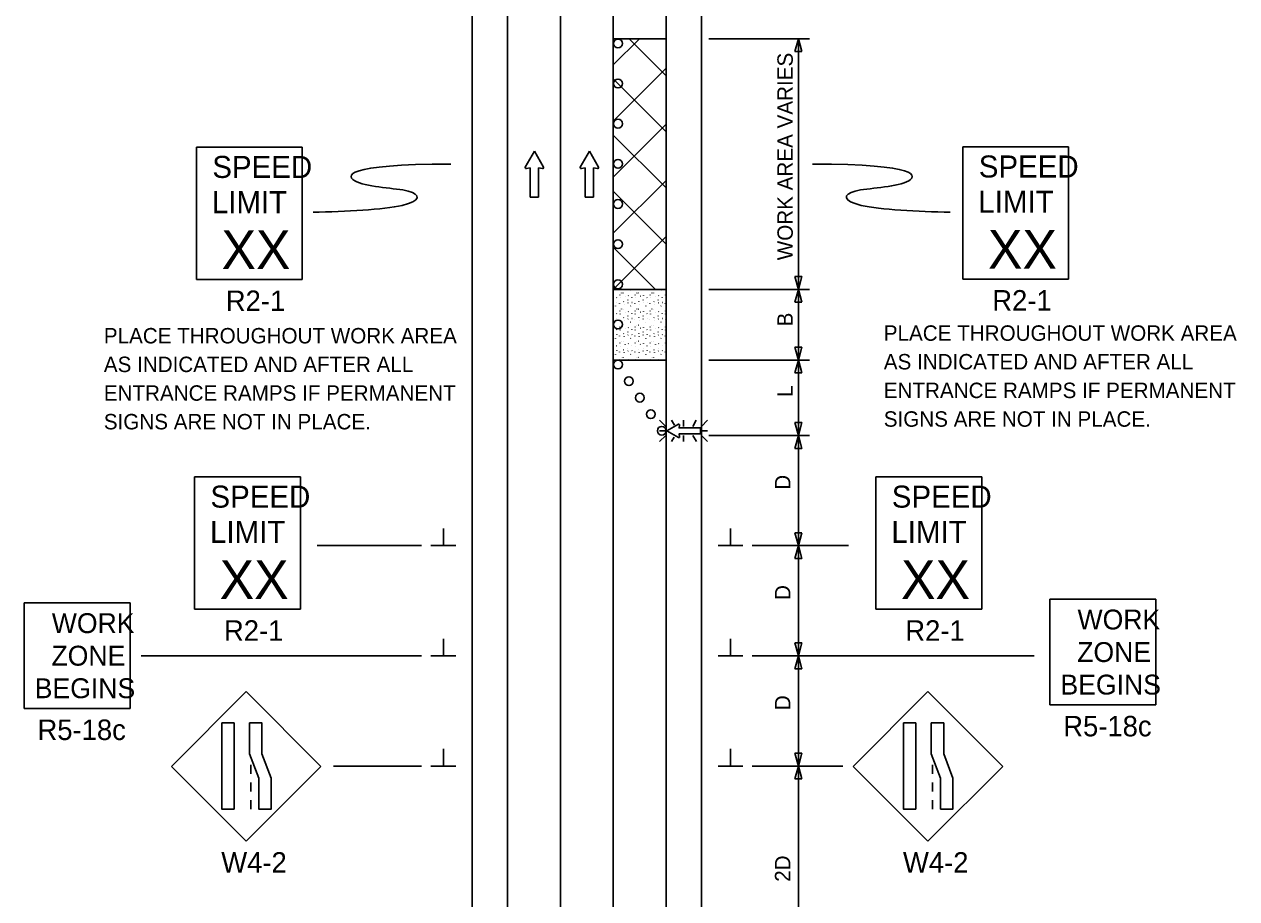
# Model space of a CAD drawing. Extents: x 16741 to 18475, y 7000 to 8315.
# Drawn here: x 16748 to 17298, y 7658 to 8055 of the extents above; entities that cross this region are included whole.
import ezdxf

# ---------------------------------------------------------------- set-up
doc = ezdxf.new("R2010")
doc.units = 0
for name, color, linetype in [('ALI_LEGAL_EX', 7, 'Continuous'), ('MT_SCRATCH_LEVEL_E', 7, 'Continuous'), ('PAVT_EDGE_EX', 7, 'Continuous'), ('TRAFFIC_SIGNS_PR', 7, 'Continuous'), ('TYPICAL_TEXT_DIMEN_PR', 7, 'Continuous')]:
    doc.layers.add(name, color=color, linetype=linetype)

msp = doc.modelspace()

# ---------------------------------------------------------------- linework, layer by layer
at = {"layer": 'ALI_LEGAL_EX'}
for p, q in [((16991.15, 8188.6), (16991.15, 7369.05)), ((17015.15, 8188.6), (17015.15, 7369.05))]:
    msp.add_line(p, q, dxfattribs=at)
for points in [[(16991.15, 7988.6), (16991.15, 7963.6)], [(17015.15, 7988.6), (17015.15, 7963.6)], [(16991.15, 7888.6), (16991.15, 7863.6)], [(16991.15, 7788.6), (16991.15, 7763.6)], [(17015.15, 7788.6), (17015.15, 7763.6)], [(16991.15, 7688.6), (16991.15, 7663.6)], [(17015.15, 7688.6), (17015.15, 7663.6)]]:
    msp.add_lwpolyline(points, dxfattribs=at)
at = {"layer": 'MT_SCRATCH_LEVEL_E'}
for p, q in [((16979.32, 7997.1), (16975.21, 7989.86)), ((16983.46, 7989.86), (16979.32, 7997.1)), ((17004.27, 7997.1), (17000.16, 7989.86)), ((17008.42, 7989.86), (17004.27, 7997.1)), ((16975.69, 7989.18), (16977.46, 7989.49)), ((16977.46, 7989.49), (16977.46, 7976.24)), ((16981.21, 7976.24), (16981.21, 7989.49)), ((16981.21, 7989.49), (16982.98, 7989.18)), ((17000.64, 7989.18), (17002.42, 7989.49)), ((17002.42, 7989.49), (17002.42, 7976.24)), ((17006.16, 7976.24), (17006.16, 7989.49)), ((17006.16, 7989.49), (17007.94, 7989.18)), ((16977.46, 7976.24), (16981.21, 7976.24)), ((17002.42, 7976.24), (17006.16, 7976.24))]:
    msp.add_line(p, q, dxfattribs=at)
for centre, start, end in [((16975.61, 7989.64), 150.4248, 279.9638), ((16983.05, 7989.64), 260.0362, 29.7731), ((17000.56, 7989.64), 150.4248, 279.9638), ((17008.01, 7989.64), 260.0362, 29.7731)]:
    msp.add_arc(centre, 0.463, start, end, dxfattribs=at)
at = {"layer": 'PAVT_EDGE_EX'}
for p, q in [((17015.15, 8314.85), (17015.15, 7485.67)), ((16951.15, 8188.6), (16951.15, 7369.05)), ((16967.15, 8188.6), (16967.15, 7369.05)), ((17039.15, 8188.6), (17039.15, 7369.05)), ((17055.15, 8188.6), (17055.15, 7369.05)), ((17039.15, 8048.11), (17015.15, 8048.11)), ((17015.15, 8048.11), (17039.15, 8048.11)), ((17015.15, 8036.2), (17027.06, 8048.11)), ((17039.15, 8031.3), (17022.34, 8048.11)), ((17039.15, 7934.38), (17039.15, 8048.11)), ((17015.15, 8010.75), (17039.15, 8034.75)), ((17039.15, 8005.84), (17015.15, 8029.84)), ((17015.15, 7985.29), (17039.15, 8009.29)), ((17039.15, 7980.39), (17015.15, 8004.39)), ((17015.15, 7959.84), (17039.15, 7983.84)), ((17039.15, 7954.93), (17015.15, 7978.93)), ((17015.15, 7934.38), (17039.15, 7958.38)), ((17034.24, 7934.38), (17015.15, 7953.47)), ((17015.15, 7934.38), (17039.15, 7934.38)), ((17015.15, 7934.38), (17039.15, 7934.38)), ((17039.15, 7934.38), (17015.15, 7934.38)), ((17015.15, 7934.38), (17015.15, 7934.38)), ((17016.08, 7934.02), (17016.13, 7934.14)), ((17022.97, 7934.02), (17023.02, 7934.14)), ((17029.85, 7934.02), (17029.91, 7934.14)), ((17036.74, 7934.02), (17036.8, 7934.14)), ((17039.15, 7902.32), (17039.15, 7934.38)), ((17016.65, 7930.7), (17016.7, 7930.62)), ((17018.1, 7931.83), (17018.15, 7931.94)), ((17018.18, 7930.56), (17018.23, 7930.48)), ((17018.86, 7932.79), (17018.92, 7932.71)), ((17019.6, 7932.76), (17019.65, 7932.68)), ((17019.82, 7928.77), (17019.87, 7928.89)), ((17020.47, 7931.38), (17020.52, 7931.3)), ((17021.75, 7929.64), (17021.8, 7929.56)), ((17021.92, 7931.53), (17021.97, 7931.65)), ((17023.54, 7930.7), (17023.59, 7930.62)), ((17024.99, 7931.83), (17025.04, 7931.94)), ((17025.07, 7930.56), (17025.12, 7930.48)), ((17025.75, 7932.79), (17025.8, 7932.71)), ((17026.49, 7932.76), (17026.54, 7932.68)), ((17026.71, 7928.77), (17026.76, 7928.89)), ((17027.36, 7931.38), (17027.41, 7931.3)), ((17028.64, 7929.64), (17028.69, 7929.56)), ((17028.81, 7931.53), (17028.86, 7931.65)), ((17030.42, 7930.7), (17030.48, 7930.62)), ((17031.88, 7931.83), (17031.93, 7931.94)), ((17031.96, 7930.56), (17032.01, 7930.48)), ((17032.64, 7932.79), (17032.69, 7932.71)), ((17033.38, 7932.76), (17033.43, 7932.68)), ((17033.6, 7928.77), (17033.65, 7928.89)), ((17034.24, 7931.38), (17034.3, 7931.3)), ((17035.52, 7929.64), (17035.57, 7929.56)), ((17035.69, 7931.53), (17035.75, 7931.65)), ((17037.31, 7930.7), (17037.36, 7930.62)), ((17038.76, 7931.83), (17038.81, 7931.94)), ((17038.84, 7930.56), (17038.89, 7930.48)), ((17016.08, 7926.74), (17016.13, 7926.86)), ((17016.65, 7923.41), (17016.7, 7923.34)), ((17016.7, 7928.49), (17016.75, 7928.41)), ((17017.98, 7927.91), (17017.99, 7927.8)), ((17018.1, 7924.54), (17018.15, 7924.66)), ((17018.18, 7923.28), (17018.23, 7923.2)), ((17018.86, 7925.5), (17018.92, 7925.42)), ((17019.6, 7925.47), (17019.65, 7925.39)), ((17020.01, 7927.57), (17020.06, 7927.49)), ((17020.47, 7924.09), (17020.52, 7924.02)), ((17021.79, 7928.24), (17021.84, 7928.36)), ((17021.92, 7924.24), (17021.97, 7924.36)), ((17022.97, 7926.74), (17023.02, 7926.86)), ((17023.54, 7923.41), (17023.59, 7923.34)), ((17023.59, 7928.49), (17023.64, 7928.41)), ((17024.87, 7927.91), (17024.88, 7927.8)), ((17024.99, 7924.54), (17025.04, 7924.66)), ((17025.07, 7923.28), (17025.12, 7923.2)), ((17025.75, 7925.5), (17025.8, 7925.42)), ((17026.49, 7925.47), (17026.54, 7925.39)), ((17026.9, 7927.57), (17026.95, 7927.49)), ((17027.36, 7924.09), (17027.41, 7924.02)), ((17028.68, 7928.24), (17028.73, 7928.36)), ((17028.81, 7924.24), (17028.86, 7924.36)), ((17029.85, 7926.74), (17029.91, 7926.86)), ((17030.42, 7923.41), (17030.48, 7923.34)), ((17030.47, 7928.49), (17030.53, 7928.41)), ((17031.76, 7927.91), (17031.77, 7927.8)), ((17031.88, 7924.54), (17031.93, 7924.66)), ((17031.96, 7923.28), (17032.01, 7923.2)), ((17032.64, 7925.5), (17032.69, 7925.42)), ((17033.38, 7925.47), (17033.43, 7925.39)), ((17033.78, 7927.57), (17033.84, 7927.49)), ((17034.24, 7924.09), (17034.3, 7924.02)), ((17035.56, 7928.24), (17035.62, 7928.36)), ((17035.69, 7924.24), (17035.75, 7924.36)), ((17036.74, 7926.74), (17036.8, 7926.86)), ((17037.31, 7923.41), (17037.36, 7923.34)), ((17037.36, 7928.49), (17037.41, 7928.41)), ((17038.64, 7927.91), (17038.66, 7927.8)), ((17038.76, 7924.54), (17038.81, 7924.66)), ((17038.84, 7923.28), (17038.89, 7923.2)), ((17016.08, 7919.45), (17016.13, 7919.57)), ((17016.7, 7921.21), (17016.75, 7921.13)), ((17017.98, 7920.63), (17017.99, 7920.51)), ((17018.86, 7918.22), (17018.92, 7918.14)), ((17019.6, 7918.19), (17019.65, 7918.11)), ((17019.82, 7921.49), (17019.87, 7921.6)), ((17020.01, 7920.29), (17020.06, 7920.21)), ((17021.75, 7922.36), (17021.8, 7922.28)), ((17021.79, 7920.95), (17021.84, 7921.07)), ((17022.97, 7919.45), (17023.02, 7919.57)), ((17023.59, 7921.21), (17023.64, 7921.13)), ((17024.87, 7920.63), (17024.88, 7920.51)), ((17025.75, 7918.22), (17025.8, 7918.14)), ((17026.49, 7918.19), (17026.54, 7918.11)), ((17026.71, 7921.49), (17026.76, 7921.6)), ((17026.9, 7920.29), (17026.95, 7920.21)), ((17028.64, 7922.36), (17028.69, 7922.28)), ((17028.68, 7920.95), (17028.73, 7921.07)), ((17029.85, 7919.45), (17029.91, 7919.57)), ((17030.47, 7921.21), (17030.53, 7921.13)), ((17031.76, 7920.63), (17031.77, 7920.51)), ((17032.64, 7918.22), (17032.69, 7918.14)), ((17033.38, 7918.19), (17033.43, 7918.11)), ((17033.6, 7921.49), (17033.65, 7921.6)), ((17033.78, 7920.29), (17033.84, 7920.21)), ((17035.52, 7922.36), (17035.57, 7922.28)), ((17035.56, 7920.95), (17035.62, 7921.07)), ((17036.74, 7919.45), (17036.8, 7919.57)), ((17037.36, 7921.21), (17037.41, 7921.13)), ((17038.64, 7920.63), (17038.66, 7920.51)), ((17016.08, 7912.17), (17016.13, 7912.28)), ((17016.65, 7916.13), (17016.7, 7916.05)), ((17016.7, 7913.92), (17016.75, 7913.84)), ((17017.98, 7913.35), (17017.99, 7913.23)), ((17018.1, 7917.26), (17018.15, 7917.37)), ((17018.18, 7915.99), (17018.23, 7915.91)), ((17019.82, 7914.2), (17019.87, 7914.32)), ((17020.01, 7913), (17020.06, 7912.92)), ((17020.47, 7916.81), (17020.52, 7916.73)), ((17021.75, 7915.07), (17021.8, 7914.99)), ((17021.79, 7913.67), (17021.84, 7913.79)), ((17021.92, 7916.96), (17021.97, 7917.07)), ((17022.97, 7912.17), (17023.02, 7912.28)), ((17023.54, 7916.13), (17023.59, 7916.05)), ((17023.59, 7913.92), (17023.64, 7913.84)), ((17024.87, 7913.35), (17024.88, 7913.23)), ((17024.99, 7917.26), (17025.04, 7917.37)), ((17025.07, 7915.99), (17025.12, 7915.91)), ((17026.71, 7914.2), (17026.76, 7914.32)), ((17026.9, 7913), (17026.95, 7912.92)), ((17027.36, 7916.81), (17027.41, 7916.73)), ((17028.64, 7915.07), (17028.69, 7914.99)), ((17028.68, 7913.67), (17028.73, 7913.79)), ((17028.81, 7916.96), (17028.86, 7917.07)), ((17029.85, 7912.17), (17029.91, 7912.28)), ((17030.42, 7916.13), (17030.48, 7916.05)), ((17030.47, 7913.92), (17030.53, 7913.84)), ((17031.76, 7913.35), (17031.77, 7913.23)), ((17031.88, 7917.26), (17031.93, 7917.37)), ((17031.96, 7915.99), (17032.01, 7915.91)), ((17033.6, 7914.2), (17033.65, 7914.32)), ((17033.78, 7913), (17033.84, 7912.92)), ((17034.24, 7916.81), (17034.3, 7916.73)), ((17035.52, 7915.07), (17035.57, 7914.99)), ((17035.56, 7913.67), (17035.62, 7913.79)), ((17035.69, 7916.96), (17035.75, 7917.07)), ((17036.74, 7912.17), (17036.8, 7912.28)), ((17037.31, 7916.13), (17037.36, 7916.05)), ((17037.36, 7913.92), (17037.41, 7913.84)), ((17038.64, 7913.35), (17038.66, 7913.23)), ((17038.76, 7917.26), (17038.81, 7917.37)), ((17038.84, 7915.99), (17038.89, 7915.91)), ((17016.65, 7908.85), (17016.7, 7908.77)), ((17016.7, 7906.64), (17016.75, 7906.56)), ((17018.1, 7909.97), (17018.15, 7910.09)), ((17018.18, 7908.7), (17018.23, 7908.63)), ((17018.86, 7910.93), (17018.92, 7910.85)), ((17019.6, 7910.9), (17019.65, 7910.82)), ((17019.82, 7906.92), (17019.87, 7907.03)), ((17020.47, 7909.52), (17020.52, 7909.45)), ((17021.75, 7907.79), (17021.8, 7907.71)), ((17021.92, 7909.67), (17021.97, 7909.79)), ((17023.54, 7908.85), (17023.59, 7908.77)), ((17023.59, 7906.64), (17023.64, 7906.56)), ((17024.99, 7909.97), (17025.04, 7910.09)), ((17025.07, 7908.7), (17025.12, 7908.63)), ((17025.75, 7910.93), (17025.8, 7910.85)), ((17026.49, 7910.9), (17026.54, 7910.82)), ((17026.71, 7906.92), (17026.76, 7907.03)), ((17027.36, 7909.52), (17027.41, 7909.45)), ((17028.64, 7907.79), (17028.69, 7907.71)), ((17028.81, 7909.67), (17028.86, 7909.79)), ((17030.42, 7908.85), (17030.48, 7908.77)), ((17030.47, 7906.64), (17030.53, 7906.56)), ((17031.88, 7909.97), (17031.93, 7910.09)), ((17031.96, 7908.7), (17032.01, 7908.63)), ((17032.64, 7910.93), (17032.69, 7910.85)), ((17033.38, 7910.9), (17033.43, 7910.82)), ((17033.6, 7906.92), (17033.65, 7907.03)), ((17034.24, 7909.52), (17034.3, 7909.45)), ((17035.52, 7907.79), (17035.57, 7907.71)), ((17035.69, 7909.67), (17035.75, 7909.79)), ((17037.31, 7908.85), (17037.36, 7908.77)), ((17037.36, 7906.64), (17037.41, 7906.56)), ((17038.76, 7909.97), (17038.81, 7910.09)), ((17038.84, 7908.7), (17038.89, 7908.63)), ((17015.15, 7902.32), (17039.15, 7902.32)), ((17015.15, 7902.32), (17039.15, 7902.32)), ((17016.08, 7904.88), (17016.13, 7905)), ((17017.98, 7906.06), (17017.99, 7905.94)), ((17018.1, 7902.69), (17018.15, 7902.8)), ((17018.86, 7903.65), (17018.92, 7903.57)), ((17019.6, 7903.62), (17019.65, 7903.54)), ((17020.01, 7905.72), (17020.06, 7905.64)), ((17021.79, 7906.39), (17021.84, 7906.5)), ((17021.92, 7902.39), (17021.97, 7902.51)), ((17022.97, 7904.88), (17023.02, 7905)), ((17024.87, 7906.06), (17024.88, 7905.94)), ((17024.99, 7902.69), (17025.04, 7902.8)), ((17025.75, 7903.65), (17025.8, 7903.57)), ((17026.49, 7903.62), (17026.54, 7903.54)), ((17026.9, 7905.72), (17026.95, 7905.64)), ((17028.68, 7906.39), (17028.73, 7906.5)), ((17028.81, 7902.39), (17028.86, 7902.51)), ((17029.85, 7904.88), (17029.91, 7905)), ((17031.76, 7906.06), (17031.77, 7905.94)), ((17031.88, 7902.69), (17031.93, 7902.8)), ((17032.64, 7903.65), (17032.69, 7903.57)), ((17033.38, 7903.62), (17033.43, 7903.54)), ((17033.78, 7905.72), (17033.84, 7905.64)), ((17035.56, 7906.39), (17035.62, 7906.5)), ((17035.69, 7902.39), (17035.75, 7902.51)), ((17036.74, 7904.88), (17036.8, 7905)), ((17038.64, 7906.06), (17038.66, 7905.94)), ((17038.76, 7902.69), (17038.81, 7902.8))]:
    msp.add_line(p, q, dxfattribs=at)
at = {"layer": 'TRAFFIC_SIGNS_PR'}
for p, q in [((16825.96, 7998.88), (16873.96, 7998.88)), ((16825.96, 7938.88), (16825.96, 7998.88)), ((16873.96, 7938.88), (16873.96, 7998.88)), ((17173.77, 7999.06), (17221.77, 7999.06)), ((17173.77, 7939.06), (17173.77, 7999.06)), ((17221.77, 7939.06), (17221.77, 7999.06)), ((16825.96, 7938.88), (16873.96, 7938.88)), ((17173.77, 7939.06), (17221.77, 7939.06)), ((17036.14, 7875.01), (17038.96, 7872.2)), ((17042.86, 7872.83), (17041.6, 7875.02)), ((17047.05, 7872.2), (17047.05, 7875.02)), ((17051.18, 7872.2), (17052.81, 7875.02)), ((17055.13, 7872.2), (17057.95, 7875.02)), ((17038.96, 7870.16), (17036.14, 7870.16)), ((17036.14, 7865.31), (17038.96, 7868.13)), ((17047.05, 7868.13), (17047.05, 7865.31)), ((17052.83, 7865.31), (17051.21, 7868.13)), ((17055.13, 7870.16), (17057.95, 7870.16)), ((17055.13, 7868.13), (17057.95, 7865.31)), ((17041.58, 7865.31), (17042.78, 7867.4)), ((16825.12, 7849.28), (16873.12, 7849.28)), ((16825.12, 7789.28), (16825.12, 7849.28)), ((16873.12, 7789.28), (16873.12, 7849.28)), ((17134.3, 7849.28), (17182.3, 7849.28)), ((17134.3, 7789.28), (17134.3, 7849.28)), ((17182.3, 7789.28), (17182.3, 7849.28)), ((16747.84, 7744.24), (16747.84, 7792.24)), ((16747.84, 7792.24), (16795.84, 7792.24)), ((16795.84, 7744.24), (16795.84, 7792.24)), ((17213.3, 7745.89), (17213.3, 7793.89)), ((17213.3, 7793.89), (17261.3, 7793.89)), ((17261.3, 7745.89), (17261.3, 7793.89)), ((16825.12, 7789.28), (16873.12, 7789.28)), ((17134.3, 7789.28), (17182.3, 7789.28)), ((16848.55, 7751.94), (16814.61, 7718)), ((16882.49, 7718), (16848.55, 7751.94)), ((17157.89, 7751.94), (17123.95, 7718)), ((17191.83, 7718), (17157.89, 7751.94)), ((16747.84, 7744.24), (16795.84, 7744.24)), ((17213.3, 7745.89), (17261.3, 7745.89)), ((16814.61, 7718), (16848.55, 7684.06)), ((16848.55, 7684.06), (16882.49, 7718)), ((16850.6, 7718.61), (16850.6, 7714.61)), ((17123.95, 7718), (17157.89, 7684.06)), ((17157.89, 7684.06), (17191.83, 7718)), ((17159.94, 7718.61), (17159.94, 7714.61)), ((16850.6, 7710.61), (16850.6, 7706.61)), ((17159.94, 7710.61), (17159.94, 7706.61)), ((16850.6, 7702.61), (16850.6, 7698.61)), ((17159.94, 7702.61), (17159.94, 7698.61))]:
    msp.add_line(p, q, dxfattribs=at)
for points in [[(17044.72, 7873.18), (17039.41, 7870.16), (17044.72, 7867.12)], [(17045.22, 7867.48), (17044.99, 7868.78), (17054.71, 7868.78), (17054.71, 7871.52), (17044.99, 7871.52), (17045.22, 7872.82)]]:
    msp.add_lwpolyline(points, dxfattribs=at)
for points in [[(16837.43, 7737.67), (16837.43, 7698.61), (16843.04, 7698.61), (16843.04, 7737.67)], [(16850.1, 7737.67), (16850.1, 7723.69), (16854.28, 7712.59), (16854.28, 7698.61), (16859.89, 7698.61), (16859.89, 7712.59), (16855.71, 7723.69), (16855.71, 7737.67)], [(17146.77, 7737.67), (17146.77, 7698.61), (17152.39, 7698.61), (17152.39, 7737.67)], [(17159.44, 7737.67), (17159.44, 7723.69), (17163.62, 7712.59), (17163.62, 7698.61), (17169.24, 7698.61), (17169.24, 7712.59), (17165.06, 7723.69), (17165.06, 7737.67)]]:
    msp.add_lwpolyline(points, close=True, dxfattribs=at)
for centre in [(17017.25, 8045.98), (17017.25, 8027.77), (17017.25, 8009.56), (17017.25, 7991.34), (17017.25, 7973.13), (17017.25, 7954.91), (17017.25, 7936.7), (17017.25, 7918.48), (17017.25, 7900.27), (17022.22, 7892.76), (17027.19, 7885.25), (17032.16, 7877.75), (17037.13, 7870.25)]:
    msp.add_circle(centre, 2, dxfattribs=at)
for centre, start, end in [((17044.89, 7872.88), 350.7308, 118.8916), ((17044.88, 7867.42), 241.4833, 9.9593)]:
    msp.add_arc(centre, 0.341, start, end, dxfattribs=at)
at = {"layer": 'TYPICAL_TEXT_DIMEN_PR'}
for p, q in [((17104.15, 8048.11), (17058.45, 8048.11)), ((17097.58, 8042.24), (17099.15, 8048.11)), ((17099.15, 7934.38), (17099.15, 8048.11)), ((17099.15, 8048.11), (17100.72, 8042.24)), ((17099.15, 8042.24), (17097.58, 8042.24)), ((17100.72, 8042.24), (17099.15, 8042.24)), ((17099.15, 7934.38), (17097.58, 7940.24)), ((17097.58, 7940.24), (17099.15, 7940.24)), ((17099.15, 7940.24), (17100.72, 7940.24)), ((17100.72, 7940.24), (17099.15, 7934.38)), ((17104.15, 7934.38), (17058.45, 7934.38)), ((17097.58, 7928.52), (17099.15, 7934.38)), ((17099.15, 7902.32), (17099.15, 7934.38)), ((17099.15, 7934.38), (17100.72, 7928.52)), ((17099.15, 7928.52), (17097.58, 7928.52)), ((17100.72, 7928.52), (17099.15, 7928.52)), ((17099.15, 7902.32), (17097.58, 7908.18)), ((17097.58, 7908.18), (17099.15, 7908.18)), ((17099.15, 7908.18), (17100.72, 7908.18)), ((17100.72, 7908.18), (17099.15, 7902.32)), ((17104.15, 7902.32), (17058.45, 7902.32)), ((17097.58, 7896.46), (17099.15, 7902.32)), ((17099.15, 7868.13), (17099.15, 7902.32)), ((17099.15, 7902.32), (17100.72, 7896.46)), ((17099.15, 7896.46), (17097.58, 7896.46)), ((17100.72, 7896.46), (17099.15, 7896.46)), ((17099.15, 7868.13), (17097.58, 7873.99)), ((17097.58, 7873.99), (17099.15, 7873.99)), ((17099.15, 7873.99), (17100.72, 7873.99)), ((17100.72, 7873.99), (17099.15, 7868.13)), ((17104.15, 7868.13), (17058.45, 7868.13)), ((17097.58, 7862.27), (17099.15, 7868.13)), ((17099.15, 7868.13), (17099.15, 7818.13)), ((17099.15, 7868.13), (17100.72, 7862.27)), ((17099.15, 7862.27), (17097.58, 7862.27)), ((17100.72, 7862.27), (17099.15, 7862.27)), ((16938.03, 7818.13), (16938.03, 7825.92)), ((17068.28, 7818.13), (17068.28, 7825.92)), ((17099.15, 7818.13), (17097.58, 7823.99)), ((17097.58, 7823.99), (17099.15, 7823.99)), ((17099.15, 7823.99), (17100.72, 7823.99)), ((17100.72, 7823.99), (17099.15, 7818.13)), ((16880.76, 7818.13), (16928.15, 7818.13)), ((16932.4, 7818.13), (16943.65, 7818.13)), ((17073.9, 7818.13), (17062.65, 7818.13)), ((17121.87, 7818.13), (17078.15, 7818.13)), ((17097.58, 7812.27), (17099.15, 7818.13)), ((17099.15, 7818.13), (17100.72, 7812.27)), ((17099.15, 7818.13), (17099.15, 7768.13)), ((17099.15, 7812.27), (17097.58, 7812.27)), ((17100.72, 7812.27), (17099.15, 7812.27)), ((16938.03, 7768.13), (16938.03, 7775.92)), ((17068.28, 7768.13), (17068.28, 7775.92)), ((17099.15, 7768.13), (17097.58, 7773.99)), ((17097.58, 7773.99), (17099.15, 7773.99)), ((17099.15, 7773.99), (17100.72, 7773.99)), ((17100.72, 7773.99), (17099.15, 7768.13)), ((16800.85, 7768.13), (16928.15, 7768.13)), ((16932.4, 7768.13), (16943.65, 7768.13)), ((17073.9, 7768.13), (17062.65, 7768.13)), ((17206.18, 7768.13), (17078.15, 7768.13)), ((17097.58, 7762.27), (17099.15, 7768.13)), ((17099.15, 7768.13), (17100.72, 7762.27)), ((17099.15, 7768.13), (17099.15, 7718.13)), ((17099.15, 7762.27), (17097.58, 7762.27)), ((17100.72, 7762.27), (17099.15, 7762.27)), ((16938.03, 7718.13), (16938.03, 7725.92)), ((17068.28, 7718.13), (17068.28, 7725.92)), ((17099.15, 7718.13), (17097.58, 7723.99)), ((17097.58, 7723.99), (17099.15, 7723.99)), ((17099.15, 7723.99), (17100.72, 7723.99)), ((17100.72, 7723.99), (17099.15, 7718.13)), ((16888.21, 7718.13), (16928.15, 7718.13)), ((16932.4, 7718.13), (16943.65, 7718.13)), ((17073.9, 7718.13), (17062.65, 7718.13)), ((17119.32, 7718.13), (17078.15, 7718.13)), ((17097.58, 7712.27), (17099.15, 7718.13)), ((17099.15, 7718.13), (17099.15, 7618.13)), ((17099.15, 7718.13), (17100.72, 7712.27)), ((17099.15, 7712.27), (17097.58, 7712.27)), ((17100.72, 7712.27), (17099.15, 7712.27))]:
    msp.add_line(p, q, dxfattribs=at)
for points in [[(16941.44, 7991.24), (16892.97, 7991.24), (16892.97, 7980.49), (16927.89, 7980.49), (16927.89, 7971.44), (16893.68, 7969.68), (16878.95, 7969.39)], [(17105.57, 7991.24), (17154.03, 7991.24), (17154.03, 7980.49), (17119.12, 7980.49), (17119.12, 7971.44), (17153.32, 7969.68), (17168.05, 7969.39)]]:
    msp.add_open_spline(points, degree=3, dxfattribs=at)

# ---------------------------------------------------------------- texts
at = {"layer": 'TRAFFIC_SIGNS_PR'}
for s, height, p in [('SPEED', 10, (16833.17, 7984.95)), ('SPEED', 10, (17180.98, 7985.14)), ('LIMIT', 10, (16832.97, 7968.95)), ('LIMIT', 10, (17180.78, 7969.14)), ('XX', 17.538, (16837.35, 7943.57)), ('XX', 17.538, (17185.16, 7943.76)), ('R2-1', 9.3, (17187.11, 7924.76)), ('R2-1', 9.3, (16839.3, 7924.58)), ('PLACE THROUGHOUT WORK AREA', 7, (17137.88, 7911.07)), ('PLACE THROUGHOUT WORK AREA', 7, (16783.95, 7909.87)), ('AS INDICATED AND AFTER ALL', 7, (16783.95, 7896.87)), ('AS INDICATED AND AFTER ALL', 7, (17137.88, 7898.07)), ('ENTRANCE RAMPS IF PERMANENT', 7, (16783.95, 7883.87)), ('ENTRANCE RAMPS IF PERMANENT', 7, (17137.88, 7885.07)), ('SIGNS ARE NOT IN PLACE.', 7, (17137.88, 7872.07)), ('SIGNS ARE NOT IN PLACE.', 7, (16783.95, 7870.87)), ('SPEED', 10, (16832.33, 7835.36)), ('SPEED', 10, (17141.51, 7835.36)), ('LIMIT', 10, (16832.13, 7819.36)), ('LIMIT', 10, (17141.31, 7819.36)), ('XX', 17.538, (16836.51, 7793.98)), ('XX', 17.538, (17145.69, 7793.98)), ('WORK', 9.021, (16760.34, 7778.45)), ('WORK', 9.021, (17225.8, 7780.1)), ('R2-1', 9.3, (16838.47, 7774.98)), ('R2-1', 9.3, (17147.65, 7774.98)), ('ZONE', 9.021, (17225.65, 7765.33)), ('ZONE', 9.021, (16760.19, 7763.69)), ('BEGINS', 9.021, (16752.6, 7748.92)), ('BEGINS', 9.021, (17218.06, 7750.57)), ('R5-18c', 9.3, (16753.85, 7729.94)), ('R5-18c', 9.3, (17219.32, 7731.59)), ('W4-2', 9.3, (16837.24, 7669.76)), ('W4-2', 9.3, (17146.59, 7669.76))]:
    msp.add_text(s, height=height, dxfattribs=at).set_placement(p)
at = {"layer": 'TYPICAL_TEXT_DIMEN_PR'}
for s, p in [('WORK AREA VARIES', (17096.59, 7947.6)), ('B', (17096.59, 7917.59)), ('L', (17096.59, 7885.61)), ('D', (17095.48, 7843.47)), ('D', (17095.48, 7793.47)), ('D', (17095.48, 7743.47)), ('2D', (17095.48, 7665.61))]:
    msp.add_text(s, height=7, rotation=90, dxfattribs=at).set_placement(p)

doc.saveas('drawing.dxf')
